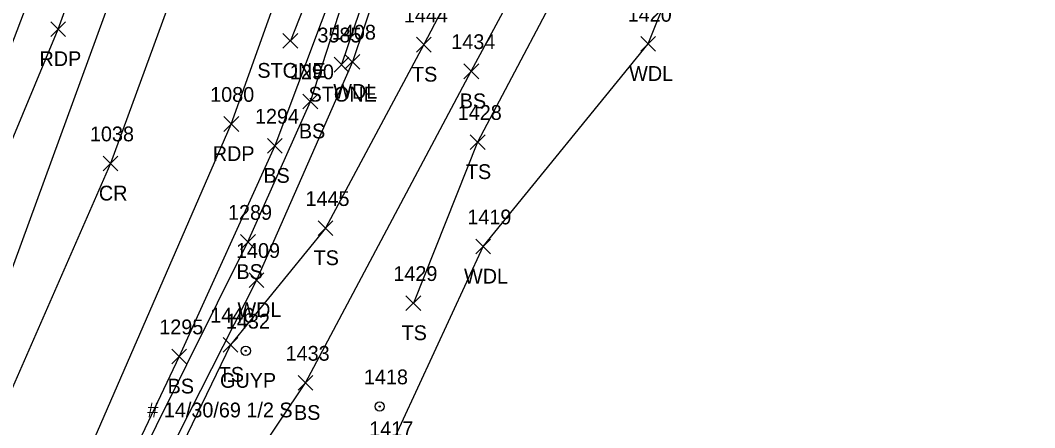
# Model space of a CAD drawing. Extents: x 1634209 to 1639641, y 608564 to 612258.
# Drawn here: x 1639323.4 to 1639460.5, y 611591.9 to 611647 of the extents above; entities that cross this region are included whole.
import ezdxf

# ---------------------------------------------------------------- set-up
doc = ezdxf.new("R2010")
doc.units = 0
for name, color, linetype in [('L_A', 7, 'Continuous'), ('L_I', 7, 'Continuous'), ('L_TIC', 7, 'Continuous'), ('LASF', 7, 'Continuous'), ('LAWA', 7, 'Continuous'), ('LELB', 7, 'Continuous'), ('P_A', 7, 'Continuous'), ('P_I', 7, 'Continuous'), ('P_TIC', 7, 'Continuous'), ('PET', 7, 'Continuous'), ('PRC', 7, 'Continuous'), ('U_A', 7, 'Continuous'), ('U_C', 7, 'Continuous'), ('U_I', 7, 'Continuous'), ('UPGW', 7, 'Continuous'), ('UW', 7, 'Continuous')]:
    doc.layers.add(name, color=color, linetype=linetype)

msp = doc.modelspace()

# ---------------------------------------------------------------- linework, layer by layer
at = {"layer": 'L_TIC'}
for points in [[(1639358.89, 611643.2), (1639360.89, 611645.2)], [(1639360.89, 611643.2), (1639358.89, 611645.2)], [(1639376.92, 611642.68), (1639378.92, 611644.68)], [(1639378.92, 611642.68), (1639376.92, 611644.68)], [(1639407.26, 611642.78), (1639409.26, 611644.78)], [(1639409.26, 611642.78), (1639407.26, 611644.78)], [(1639365.81, 611639.98), (1639367.81, 611641.98)], [(1639367.81, 611639.98), (1639365.81, 611641.98)], [(1639367.27, 611640.36), (1639369.27, 611642.36)], [(1639369.27, 611640.36), (1639367.27, 611642.36)], [(1639383.34, 611639.08), (1639385.34, 611641.08)], [(1639385.34, 611639.08), (1639383.34, 611641.08)], [(1639361.59, 611635), (1639363.59, 611637)], [(1639363.59, 611635), (1639361.59, 611637)], [(1639356.8, 611629), (1639358.8, 611631)], [(1639358.8, 611629), (1639356.8, 611631)], [(1639384.2, 611629.51), (1639386.2, 611631.51)], [(1639386.2, 611629.51), (1639384.2, 611631.51)], [(1639363.63, 611617.87), (1639365.63, 611619.87)], [(1639365.63, 611617.87), (1639363.63, 611619.87)], [(1639353.16, 611616), (1639355.16, 611618)], [(1639355.16, 611616), (1639353.16, 611618)], [(1639384.94, 611615.38), (1639386.94, 611617.38)], [(1639386.94, 611615.38), (1639384.94, 611617.38)], [(1639354.32, 611610.85), (1639356.32, 611612.85)], [(1639356.32, 611610.85), (1639354.32, 611612.85)], [(1639375.51, 611607.73), (1639377.51, 611609.73)], [(1639377.51, 611607.73), (1639375.51, 611609.73)], [(1639350.81, 611602.1), (1639352.81, 611604.1)], [(1639352.81, 611602.1), (1639350.81, 611604.1)], [(1639343.86, 611600.52), (1639345.86, 611602.52)], [(1639345.86, 611600.52), (1639343.86, 611602.52)], [(1639360.94, 611596.95), (1639362.94, 611598.95)], [(1639362.94, 611596.95), (1639360.94, 611598.95)]]:
    msp.add_lwpolyline(points, dxfattribs=at)
at = {"layer": 'LASF'}
for points in [[(1639558.56, 612130.45), (1639552.86, 612120.18), (1639541.01, 612102.18), (1639527.49, 612085.59), (1639505.85, 612048.28), (1639489.98, 612019.2), (1639472.04, 611983.89), (1639455.22, 611944.85), (1639439.42, 611901.14), (1639424.97, 611855.61), (1639411.65, 611810.44), (1639400.31, 611769.99), (1639387.4, 611727.33), (1639377.22, 611693.8), (1639367.21, 611662.75), (1639359.89, 611644.2)], [(1639564.17, 612127.3), (1639559.55, 612115.01), (1639546.48, 612097.15), (1639532.98, 612081.91), (1639511.96, 612045.66), (1639494.66, 612017.18), (1639476.15, 611980.34), (1639460.76, 611943.45), (1639444.67, 611898.59), (1639430.04, 611853.19), (1639417.13, 611807.26), (1639407.25, 611767.41), (1639395.02, 611725.74), (1639384.78, 611692.04), (1639373.34, 611660.29), (1639366.81, 611640.98)]]:
    msp.add_lwpolyline(points, dxfattribs=at)
at = {"layer": 'LAWA'}
msp.add_lwpolyline([(1639441.05, 611876.68), (1639428.25, 611845.92), (1639421.82, 611821.54), (1639414.82, 611793.13), (1639407.98, 611755.62), (1639398.09, 611722.15), (1639389.22, 611695.21), (1639379.03, 611668.1), (1639373.01, 611655.47), (1639368.27, 611641.36), (1639355.32, 611611.85), (1639341.64, 611584.95), (1639331.87, 611563.95), (1639326.04, 611548.05), (1639331.93, 611542.26), (1639351.96, 611561.26), (1639372.68, 611587.74), (1639385.94, 611616.38), (1639408.26, 611643.78), (1639423.94, 611682.92), (1639440.86, 611711.19), (1639451.78, 611745.34)], dxfattribs=at)
at = {"layer": 'LELB'}
for points in [[(1639444.11, 611769.17), (1639434.73, 611747.93), (1639421.15, 611721.63), (1639402.1, 611695.55), (1639388.08, 611663.08), (1639377.92, 611643.68), (1639364.63, 611618.87), (1639351.81, 611603.1), (1639339.53, 611577.73), (1639327.06, 611550.1)], [(1639309.63, 611764.24), (1639299.64, 611734.07), (1639289.6, 611701.48), (1639307.06, 611683.24), (1639321.98, 611670.4), (1639326.57, 611669.97), (1639326.59, 611655.19), (1639316.06, 611627.66)], [(1639328.53, 611549.34), (1639340.68, 611566.19), (1639361.94, 611597.95), (1639384.34, 611640.08), (1639404.07, 611676.75), (1639420.55, 611705.41), (1639435.23, 611731.96), (1639444.04, 611752.15)], [(1639448.38, 611747.41), (1639431.66, 611713.79), (1639419.2, 611690.7), (1639399.36, 611657.42), (1639385.2, 611630.51), (1639376.51, 611608.73)], [(1639319.01, 611537.13), (1639316.51, 611543.95), (1639324.77, 611554.65), (1639337.69, 611583.96), (1639354.16, 611617), (1639362.59, 611636), (1639368.58, 611654.51), (1639367.12, 611654.87), (1639357.8, 611630), (1639344.86, 611601.52), (1639331.86, 611574.07), (1639320.88, 611550.11)]]:
    msp.add_lwpolyline(points, dxfattribs=at)
at = {"layer": 'P_TIC'}
for points in [[(1639327.5, 611644.78), (1639329.5, 611646.78)], [(1639329.5, 611644.78), (1639327.5, 611646.78)], [(1639350.91, 611631.95), (1639352.91, 611633.95)], [(1639352.91, 611631.95), (1639350.91, 611633.95)], [(1639334.57, 611626.61), (1639336.57, 611628.61)], [(1639336.57, 611626.61), (1639334.57, 611628.61)]]:
    msp.add_lwpolyline(points, dxfattribs=at)
at = {"layer": 'PET'}
for points in [[(1639245.26, 611428.04), (1639265.27, 611462.65), (1639285.72, 611496.98), (1639297.96, 611518.63), (1639312.46, 611545.86), (1639331.24, 611585.47), (1639351.91, 611632.95), (1639369.29, 611681.55), (1639385.15, 611732.94), (1639399.72, 611782.78), (1639415.55, 611836.4), (1639431.27, 611887.12), (1639449.51, 611937.71), (1639468.81, 611983.24), (1639484.71, 612016.46), (1639503.95, 612051.42), (1639527.63, 612090.72), (1639556.4, 612135.38), (1639588.32, 612182.52)], [(1639220.96, 611441.47), (1639247.22, 611483.75), (1639268.21, 611519.52), (1639285.57, 611551.38), (1639309.59, 611600.33), (1639328.5, 611645.78), (1639344.08, 611688.66), (1639358.64, 611735.43), (1639372.55, 611782.94), (1639389.96, 611841.92), (1639405.55, 611892.01), (1639422.64, 611939.83), (1639441.75, 611985.91), (1639461.99, 612028.31)]]:
    msp.add_lwpolyline(points, dxfattribs=at)
at = {"layer": 'PRC'}
msp.add_lwpolyline([(1639473.49, 612022.53), (1639453.52, 611981.45), (1639432.7, 611930.67), (1639416.88, 611885.46), (1639401.13, 611834.82), (1639385.48, 611780.16), (1639369.66, 611726.72), (1639353.84, 611677.52), (1639335.57, 611627.61), (1639314.72, 611580.03), (1639292.65, 611536.14), (1639275.3, 611504.78), (1639250.46, 611462.84), (1639222.36, 611418.18)], dxfattribs=at)
at = {"layer": 'UPGW'}
for centre, radius in [((1639353.86, 611602.29), 0.625), ((1639353.86, 611602.29), 0.0833), ((1639371.96, 611594.76), 0.625), ((1639371.96, 611594.76), 0.0833)]:
    msp.add_circle(centre, radius, dxfattribs=at)
at = {"layer": 'UW'}
msp.add_lwpolyline([(1639594.99, 612226.51), (1639569.63, 612190.35), (1639550.67, 612164.48), (1639527.14, 612128.9), (1639506.92, 612097.5), (1639485.03, 612062.24), (1639463.29, 612024.05), (1639448.18, 611991.92), (1639428.21, 611945.59), (1639409.39, 611896.28), (1639395.47, 611852.57), (1639388.14, 611826.68), (1639366.36, 611747.21), (1639350.92, 611692.02), (1639316.38, 611597.42), (1639292.15, 611550.99), (1639279.15, 611528.72), (1639253.95, 611487.01), (1639229.78, 611449.06), (1639200.46, 611402.5), (1639172.27, 611358.67), (1639148.82, 611320.98)], dxfattribs=at)

# ---------------------------------------------------------------- texts
at = {"layer": 'L_A'}
for s, p in [('STONE', (1639355.43, 611639.2)), ('TS', (1639376.33, 611638.68)), ('WDL', (1639405.68, 611638.78)), ('STONE', (1639362.35, 611635.98)), ('WDL', (1639365.69, 611636.36)), ('BS', (1639382.78, 611635.08)), ('BS', (1639361.04, 611631)), ('BS', (1639356.24, 611625)), ('TS', (1639383.61, 611625.51)), ('TS', (1639363.03, 611613.87)), ('BS', (1639352.6, 611612)), ('WDL', (1639383.36, 611611.38)), ('WDL', (1639352.74, 611606.85)), ('TS', (1639374.92, 611603.73)), ('TS', (1639350.21, 611598.1)), ('BS', (1639343.3, 611596.52)), ('BS', (1639360.38, 611592.95))]:
    msp.add_text(s, height=2, dxfattribs=at).set_placement(p)
at = {"layer": 'L_I'}
for s, p in [('1444', (1639375.23, 611646.68)), ('1420', (1639405.48, 611646.78)), ('3585', (1639363.55, 611643.98)), ('1408', (1639365.5, 611644.36)), ('1434', (1639381.64, 611643.08)), ('1290', (1639359.82, 611639)), ('1294', (1639355.11, 611633)), ('1428', (1639382.51, 611633.51)), ('1445', (1639361.93, 611621.87)), ('1289', (1639351.46, 611620)), ('1419', (1639383.81, 611619.38)), ('1409', (1639352.54, 611614.85)), ('1429', (1639373.81, 611611.73)), ('1446', (1639349.06, 611606.1)), ('1295', (1639342.17, 611604.52)), ('1433', (1639359.25, 611600.95)), ('1417', (1639370.55, 611590.74))]:
    msp.add_text(s, height=2, dxfattribs=at).set_placement(p)
at = {"layer": 'P_A'}
for s, p in [('RDP', (1639325.98, 611640.78)), ('RDP', (1639349.4, 611627.95)), ('CR', (1639334.01, 611622.61))]:
    msp.add_text(s, height=2, dxfattribs=at).set_placement(p)
at = {"layer": 'P_I'}
for s, p in [('1080', (1639349.05, 611635.95)), ('1038', (1639332.8, 611630.61))]:
    msp.add_text(s, height=2, dxfattribs=at).set_placement(p)
at = {"layer": 'U_A'}
msp.add_text('GUYP', height=2, dxfattribs=at).set_placement((1639350.38, 611597.29))
at = {"layer": 'U_C'}
msp.add_text('# 14/30/69 1/2 S', height=2, dxfattribs=at).set_placement((1639340.56, 611593.29))
at = {"layer": 'U_I'}
for s, p in [('1432', (1639351.17, 611605.29)), ('1418', (1639369.83, 611597.76))]:
    msp.add_text(s, height=2, dxfattribs=at).set_placement(p)

doc.saveas('drawing.dxf')
